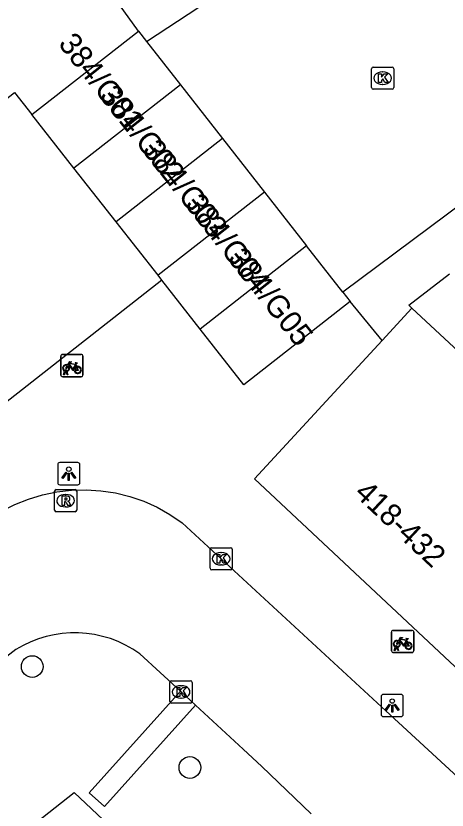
# Model space of a CAD drawing. Extents: x 159222 to 160346, y 381249 to 382166.
# Drawn here: x 159675.49 to 159694.93, y 381616.91 to 381652.7 of the extents above; entities that cross this region are included whole.
import ezdxf

# ---------------------------------------------------------------- set-up
doc = ezdxf.new("R2010")
doc.units = 0
for name, color, linetype in [('IMGEO_Boom', 7, 'Continuous'), ('IMGEO_Fietsenrek', 7, 'Continuous'), ('IMGEO_Groenvoorziening', 7, 'Continuous'), ('IMGEO_Kolk', 7, 'Continuous'), ('IMGEO_Lichtpunt', 7, 'Continuous'), ('IMGEO_Pand', 7, 'Continuous'), ('IMGEO_Pand_nummerreeks', 7, 'Continuous'), ('IMGEO_Rijbaan_lokaal_open', 7, 'Continuous'), ('IMGEO_Rioolput', 7, 'Continuous'), ('IMGEO_Voetpad_open', 7, 'Continuous')]:
    doc.layers.add(name, color=color, linetype=linetype)

msp = doc.modelspace()

# ---------------------------------------------------------------- linework, layer by layer
at = {"layer": 'IMGEO_Boom'}
for centre in [(159676.225, 381623.376), (159683.333, 381618.828)]:
    msp.add_circle(centre, 0.489, dxfattribs=at)
at = {"layer": 'IMGEO_Fietsenrek'}
for p, q in [((159677.514, 381636.518), (159677.514, 381637.359)), ((159677.514, 381637.359), (159677.514, 381636.518)), ((159677.589, 381637.443), (159678.43, 381637.443)), ((159678.43, 381637.443), (159677.589, 381637.443)), ((159678.514, 381637.368), (159678.514, 381636.527)), ((159678.514, 381636.527), (159678.514, 381637.368)), ((159678.201, 381636.992), (159678.237, 381636.897)), ((159677.641, 381636.527), (159677.68, 381636.687)), ((159677.675, 381636.527), (159677.641, 381636.527)), ((159677.71, 381636.675), (159677.675, 381636.527)), ((159677.752, 381636.699), (159677.751, 381636.703)), ((159677.793, 381636.527), (159677.759, 381636.669)), ((159677.783, 381636.71), (159677.784, 381636.703)), ((159677.791, 381636.673), (159677.826, 381636.527)), ((159677.826, 381636.527), (159677.793, 381636.527)), ((159678.439, 381636.443), (159677.598, 381636.443)), ((159677.598, 381636.443), (159678.439, 381636.443)), ((159692.424, 381624.085), (159692.424, 381624.926)), ((159692.424, 381624.926), (159692.424, 381624.085)), ((159692.499, 381625.01), (159693.34, 381625.01)), ((159693.34, 381625.01), (159692.499, 381625.01)), ((159693.424, 381624.935), (159693.424, 381624.094)), ((159693.424, 381624.094), (159693.424, 381624.935)), ((159693.111, 381624.559), (159693.147, 381624.464)), ((159693.349, 381624.01), (159692.508, 381624.01)), ((159692.508, 381624.01), (159693.349, 381624.01)), ((159692.551, 381624.094), (159692.59, 381624.254)), ((159692.585, 381624.094), (159692.551, 381624.094)), ((159692.62, 381624.242), (159692.585, 381624.094)), ((159692.662, 381624.266), (159692.661, 381624.27)), ((159692.703, 381624.094), (159692.669, 381624.236)), ((159692.693, 381624.277), (159692.694, 381624.27)), ((159692.701, 381624.24), (159692.736, 381624.094)), ((159692.736, 381624.094), (159692.703, 381624.094))]:
    msp.add_line(p, q, dxfattribs=at)
for points in [[(159677.848, 381636.917), (159677.796, 381636.827), (159677.756, 381636.802), (159677.757, 381636.849), (159677.812, 381636.943)], [(159677.827, 381636.969), (159677.922, 381637.133), (159678.008, 381637.119), (159678.01, 381637.11), (159677.954, 381637.099), (159677.927, 381637.054), (159678.183, 381637.013)], [(159678.123, 381636.725), (159678.073, 381636.725), (159677.882, 381636.976), (159677.863, 381636.944)], [(159678.17, 381636.988), (159677.913, 381637.029), (159677.896, 381637), (159678.063, 381636.78), (159678.17, 381636.988)], [(159678.218, 381636.89), (159678.188, 381636.967), (159678.079, 381636.749), (159678.122, 381636.749)], [(159678.152, 381636.749), (159678.272, 381636.748), (159678.228, 381636.862)], [(159678.248, 381636.869), (159678.303, 381636.724), (159678.153, 381636.724)], [(159678.183, 381637.013), (159678.208, 381637.062), (159678.202, 381637.066), (159678.179, 381637.07), (159678.167, 381637.077), (159678.166, 381637.08), (159678.168, 381637.085), (159678.263, 381637.07), (159678.265, 381637.06), (159678.255, 381637.047), (159678.243, 381637.041), (159678.229, 381637.047), (159678.201, 381636.992)], [(159692.737, 381624.536), (159692.832, 381624.7), (159692.918, 381624.686), (159692.92, 381624.677), (159692.864, 381624.666), (159692.837, 381624.621), (159693.093, 381624.58)], [(159692.758, 381624.484), (159692.706, 381624.394), (159692.666, 381624.369), (159692.667, 381624.416), (159692.722, 381624.51)], [(159693.033, 381624.292), (159692.983, 381624.292), (159692.792, 381624.543), (159692.773, 381624.511)], [(159693.08, 381624.555), (159692.823, 381624.596), (159692.806, 381624.567), (159692.973, 381624.347), (159693.08, 381624.555)], [(159693.128, 381624.457), (159693.098, 381624.534), (159692.989, 381624.316), (159693.032, 381624.316)], [(159693.062, 381624.316), (159693.182, 381624.315), (159693.138, 381624.429)], [(159693.158, 381624.436), (159693.213, 381624.291), (159693.063, 381624.291)], [(159693.093, 381624.58), (159693.118, 381624.629), (159693.112, 381624.633), (159693.089, 381624.637), (159693.077, 381624.644), (159693.076, 381624.647), (159693.078, 381624.652), (159693.173, 381624.637), (159693.175, 381624.627), (159693.165, 381624.614), (159693.153, 381624.608), (159693.139, 381624.614), (159693.111, 381624.559)]]:
    msp.add_lwpolyline(points, dxfattribs=at)
for centre, radius, start, end in [((159677.592, 381637.365), 0.0779, 92.4484, 184.2845), ((159677.592, 381637.365), 0.0779, 92.4484, 184.2845), ((159678.436, 381637.365), 0.0779, 2.4484, 94.2845), ((159678.436, 381637.365), 0.0779, 2.4484, 94.2845), ((159677.754, 381636.828), 0.159, 62.6766, 242.1369), ((159677.754, 381636.828), 0.129, 63.3192, 238.903), ((159677.754, 381636.828), 0.129, 283.6043, 43.4302), ((159677.754, 381636.828), 0.159, 283.5766, 46.6042), ((159678.281, 381636.744), 0.159, 113.3408, 178.3217), ((159678.281, 381636.744), 0.159, 187.0065, 105.7708), ((159678.281, 381636.744), 0.129, 113.923, 177.9556), ((159678.281, 381636.744), 0.129, 188.6715, 104.5883), ((159677.592, 381636.521), 0.0779, 182.4484, 274.2845), ((159677.592, 381636.521), 0.0779, 182.4484, 274.2845), ((159677.734, 381636.699), 0.0499, 12.8025, 158.6934), ((159677.754, 381636.828), 0.159, 253.9967, 271.7867), ((159677.734, 381636.699), 0.0174, 12.8025, 163.4502), ((159677.754, 381636.828), 0.129, 253.415, 269.0204), ((159678.436, 381636.521), 0.0779, 272.4484, 4.2845), ((159678.436, 381636.521), 0.0779, 272.4484, 4.2845), ((159692.502, 381624.932), 0.0779, 92.4484, 184.2845), ((159692.502, 381624.932), 0.0779, 92.4484, 184.2845), ((159693.346, 381624.932), 0.0779, 2.4484, 94.2845), ((159693.346, 381624.932), 0.0779, 2.4484, 94.2845), ((159692.664, 381624.395), 0.159, 62.6766, 242.1369), ((159692.664, 381624.395), 0.129, 63.3192, 238.903), ((159692.644, 381624.266), 0.0499, 12.8025, 158.6934), ((159692.664, 381624.395), 0.129, 283.6043, 43.4302), ((159692.664, 381624.395), 0.159, 283.5766, 46.6042), ((159693.191, 381624.311), 0.159, 113.3408, 178.3217), ((159693.191, 381624.311), 0.159, 187.0065, 105.7708), ((159693.191, 381624.311), 0.129, 113.923, 177.9556), ((159693.191, 381624.311), 0.129, 188.6715, 104.5883), ((159692.502, 381624.088), 0.0779, 182.4484, 274.2845), ((159692.502, 381624.088), 0.0779, 182.4484, 274.2845), ((159692.664, 381624.395), 0.159, 253.9967, 271.7867), ((159692.644, 381624.266), 0.0174, 12.8025, 163.4502), ((159692.664, 381624.395), 0.129, 253.415, 269.0204), ((159693.346, 381624.088), 0.0779, 272.4484, 4.2845), ((159693.346, 381624.088), 0.0779, 272.4484, 4.2845)]:
    msp.add_arc(centre, radius, start, end, dxfattribs=at)
at = {"layer": 'IMGEO_Groenvoorziening'}
msp.add_lwpolyline([(159666.889, 381608.847), (159678.112, 381617.696), (159680.462, 381615.488)], dxfattribs=at)
at = {"layer": 'IMGEO_Kolk'}
for p, q in [((159691.523, 381649.47), (159691.523, 381650.322)), ((159691.598, 381650.396), (159692.45, 381650.396)), ((159692.011, 381650.176), (159692.036, 381650.176)), ((159692.524, 381650.322), (159692.524, 381649.47)), ((159692.45, 381649.396), (159691.598, 381649.396)), ((159692.034, 381649.616), (159692.009, 381649.616)), ((159684.242, 381627.809), (159684.242, 381628.661)), ((159684.317, 381628.735), (159685.169, 381628.735)), ((159685.243, 381628.661), (159685.243, 381627.809)), ((159684.73, 381628.515), (159684.755, 381628.515)), ((159684.753, 381627.955), (159684.728, 381627.955)), ((159685.169, 381627.735), (159684.317, 381627.735)), ((159682.436, 381621.808), (159682.436, 381622.66)), ((159682.511, 381622.734), (159683.363, 381622.734)), ((159682.924, 381622.514), (159682.949, 381622.514)), ((159683.437, 381622.66), (159683.437, 381621.808)), ((159682.947, 381621.954), (159682.922, 381621.954)), ((159683.363, 381621.734), (159682.511, 381621.734))]:
    msp.add_line(p, q, dxfattribs=at)
for points in [[(159691.523, 381649.47), (159691.523, 381650.322)], [(159691.598, 381650.396), (159692.45, 381650.396)], [(159691.844, 381650.096), (159691.967, 381650.096), (159691.967, 381649.945), (159692.097, 381650.096), (159692.261, 381650.096), (159692.115, 381649.945), (159692.268, 381649.696), (159692.116, 381649.696), (159692.031, 381649.86), (159691.967, 381649.793), (159691.967, 381649.696), (159691.844, 381649.696), (159691.844, 381650.096)], [(159692.524, 381650.322), (159692.524, 381649.47)], [(159692.45, 381649.396), (159691.598, 381649.396)], [(159684.242, 381627.809), (159684.242, 381628.661)], [(159684.317, 381628.735), (159685.169, 381628.735)], [(159685.243, 381628.661), (159685.243, 381627.809)], [(159684.563, 381628.435), (159684.686, 381628.435), (159684.686, 381628.284), (159684.816, 381628.435), (159684.98, 381628.435), (159684.834, 381628.284), (159684.987, 381628.035), (159684.835, 381628.035), (159684.75, 381628.199), (159684.686, 381628.132), (159684.686, 381628.035), (159684.563, 381628.035), (159684.563, 381628.435)], [(159685.169, 381627.735), (159684.317, 381627.735)], [(159682.436, 381621.808), (159682.436, 381622.66)], [(159682.511, 381622.734), (159683.363, 381622.734)], [(159683.437, 381622.66), (159683.437, 381621.808)], [(159682.757, 381622.434), (159682.88, 381622.434), (159682.88, 381622.283), (159683.01, 381622.434), (159683.174, 381622.434), (159683.028, 381622.283), (159683.181, 381622.034), (159683.029, 381622.034), (159682.944, 381622.198), (159682.88, 381622.131), (159682.88, 381622.034), (159682.757, 381622.034), (159682.757, 381622.434)], [(159683.363, 381621.734), (159682.511, 381621.734)]]:
    msp.add_lwpolyline(points, dxfattribs=at)
for centre, start, end in [((159691.6, 381650.32), 91.552, 178.448), ((159691.6, 381650.32), 91.552, 178.448), ((159692.448, 381650.32), 1.552, 88.448), ((159692.448, 381650.32), 1.552, 88.448), ((159691.6, 381649.472), 181.552, 268.448), ((159691.6, 381649.472), 181.552, 268.448), ((159692.448, 381649.472), 271.552, 358.448), ((159692.448, 381649.472), 271.552, 358.448), ((159684.319, 381628.659), 91.552, 178.448), ((159684.319, 381628.659), 91.552, 178.448), ((159685.167, 381628.659), 1.552, 88.448), ((159685.167, 381628.659), 1.552, 88.448), ((159684.319, 381627.811), 181.552, 268.448), ((159684.319, 381627.811), 181.552, 268.448), ((159685.167, 381627.811), 271.552, 358.448), ((159685.167, 381627.811), 271.552, 358.448), ((159682.513, 381622.658), 91.552, 178.448), ((159682.513, 381622.658), 91.552, 178.448), ((159683.361, 381622.658), 1.552, 88.448), ((159683.361, 381622.658), 1.552, 88.448), ((159682.513, 381621.81), 181.552, 268.448), ((159682.513, 381621.81), 181.552, 268.448), ((159683.361, 381621.81), 271.552, 358.448), ((159683.361, 381621.81), 271.552, 358.448)]:
    msp.add_arc(centre, 0.0765, start, end, dxfattribs=at)
for centre, major_axis, ratio, start_param, end_param in [((159692.01, 381649.896), (-0.387, 0.002), 0.722429, 4.712389, 7.853982), ((159692.035, 381649.896), (-0.39, 0.002), 0.717154, 1.570796, 4.712389), ((159684.729, 381628.235), (-0.387, 0.002), 0.722429, 4.712389, 7.853982), ((159684.754, 381628.235), (-0.39, 0.002), 0.717154, 1.570796, 4.712389), ((159682.923, 381622.234), (-0.387, 0.002), 0.722429, 4.712389, 7.853982), ((159682.948, 381622.234), (-0.39, 0.002), 0.717154, 1.570796, 4.712389)]:
    msp.add_ellipse(centre, major_axis=major_axis, ratio=ratio, start_param=start_param, end_param=end_param, dxfattribs=at)
at = {"layer": 'IMGEO_Lichtpunt'}
for p, q in [((159678.277, 381632.57), (159677.469, 381632.57)), ((159678.277, 381632.57), (159677.469, 381632.57)), ((159677.375, 381632.475), (159677.375, 381631.668)), ((159677.375, 381632.475), (159677.375, 381631.668)), ((159678.371, 381631.668), (159678.371, 381632.475)), ((159678.371, 381631.668), (159678.371, 381632.475)), ((159677.469, 381631.574), (159678.277, 381631.574)), ((159677.469, 381631.574), (159678.277, 381631.574)), ((159691.957, 381622.025), (159691.957, 381621.218)), ((159691.957, 381622.025), (159691.957, 381621.218)), ((159692.859, 381622.12), (159692.051, 381622.12)), ((159692.859, 381622.12), (159692.051, 381622.12)), ((159692.953, 381621.218), (159692.953, 381622.025)), ((159692.953, 381621.218), (159692.953, 381622.025)), ((159692.051, 381621.124), (159692.859, 381621.124)), ((159692.051, 381621.124), (159692.859, 381621.124))]:
    msp.add_line(p, q, dxfattribs=at)
for points in [[(159677.749, 381632.139), (159677.788, 381632.111), (159677.6, 381631.849), (159677.562, 381631.876), (159677.749, 381632.139)], [(159677.851, 381632.091), (159677.898, 381632.091), (159677.898, 381631.769), (159677.851, 381631.769), (159677.851, 381632.091)], [(159677.961, 381632.111), (159677.999, 381632.138), (159678.186, 381631.876), (159678.147, 381631.848), (159677.961, 381632.111)], [(159692.331, 381621.689), (159692.37, 381621.661), (159692.182, 381621.399), (159692.144, 381621.426), (159692.331, 381621.689)], [(159692.433, 381621.641), (159692.48, 381621.641), (159692.48, 381621.319), (159692.433, 381621.319), (159692.433, 381621.641)], [(159692.543, 381621.661), (159692.581, 381621.688), (159692.768, 381621.426), (159692.729, 381621.398), (159692.543, 381621.661)]]:
    msp.add_lwpolyline(points, dxfattribs=at)
for centre in [(159677.874, 381632.273), (159692.456, 381621.823)]:
    msp.add_circle(centre, 0.0994, dxfattribs=at)
for centre, start, end in [((159677.469, 381632.475), 90, 180), ((159677.469, 381632.475), 90, 180), ((159678.277, 381632.475), 0, 90), ((159678.277, 381632.475), 0, 90), ((159677.469, 381631.668), 180, 270), ((159677.469, 381631.668), 180, 270), ((159678.277, 381631.668), 270, 0), ((159678.277, 381631.668), 270, 360), ((159692.051, 381622.025), 90, 180), ((159692.051, 381622.025), 90, 180), ((159692.859, 381622.025), 0, 90), ((159692.859, 381622.025), 0, 90), ((159692.051, 381621.218), 180, 270), ((159692.051, 381621.218), 180, 270), ((159692.859, 381621.218), 270, 0), ((159692.859, 381621.218), 270, 360)]:
    msp.add_arc(centre, 0.0946, start, end, dxfattribs=at)
at = {"layer": 'IMGEO_Pand'}
for points in [[(159676.208, 381648.256), (159681.011, 381652.018)], [(159681.011, 381652.018), (159681.38, 381651.547)], [(159681.38, 381651.547), (159682.907, 381649.597)], [(159682.907, 381649.597), (159678.108, 381645.838)], [(159682.907, 381649.597), (159684.803, 381647.176)], [(159672.749, 381647.16), (159675.425, 381649.256), (159676.208, 381648.256)], [(159678.108, 381645.838), (159676.208, 381648.256)], [(159684.803, 381647.176), (159680.008, 381643.421)], [(159684.803, 381647.176), (159686.691, 381644.766)], [(159680.008, 381643.421), (159678.108, 381645.838)], [(159686.691, 381644.766), (159681.899, 381641.013)], [(159686.691, 381644.766), (159688.595, 381642.335)], [(159681.899, 381641.013), (159680.008, 381643.421)], [(159688.595, 381642.335), (159683.804, 381638.582)], [(159690.231, 381640.246), (159688.595, 381642.335)], [(159682.069, 381640.797), (159670.12, 381631.438)], [(159682.069, 381640.797), (159681.899, 381641.013)], [(159683.804, 381638.582), (159682.069, 381640.797)], [(159690.231, 381640.246), (159690.556, 381639.831)], [(159690.556, 381639.831), (159685.765, 381636.079), (159683.804, 381638.582)], [(159691.997, 381638.077), (159693.343, 381639.536)], [(159704.334, 381629.328), (159693.343, 381639.536)], [(159697.195, 381621.587), (159686.25, 381631.845), (159691.997, 381638.077)]]:
    msp.add_lwpolyline(points, dxfattribs=at)
at = {"layer": 'IMGEO_Rijbaan_lokaal_open'}
for points in [[(159681.38, 381651.547), (159686.578, 381654.975), (159698.504, 381664.326), (159725.995, 381685.842), (159726.077, 381685.887), (159726.578, 381686.129), (159727.1, 381686.326), (159727.636, 381686.475), (159728.184, 381686.575), (159728.739, 381686.627), (159729.296, 381686.628), (159729.85, 381686.58), (159730.399, 381686.482), (159730.936, 381686.336), (159731.459, 381686.142), (159731.961, 381685.903), (159732.441, 381685.619), (159732.893, 381685.294), (159765.564, 381655.029), (159765.97, 381654.692), (159766.405, 381654.392), (159766.864, 381654.132), (159767.345, 381653.914), (159767.844, 381653.74)], [(159701.061, 381645.68), (159700.652, 381645.814), (159700.232, 381645.91), (159699.805, 381645.969), (159699.375, 381645.989), (159698.945, 381645.971), (159698.518, 381645.914), (159698.098, 381645.82), (159697.688, 381645.688), (159697.301, 381645.525), (159690.231, 381640.246)], [(159638.593, 381602.067), (159674.232, 381629.981), (159674.292, 381630.023), (159674.853, 381630.376), (159675.443, 381630.678), (159676.058, 381630.926), (159676.692, 381631.119), (159677.342, 381631.253), (159678, 381631.329), (159678.663, 381631.346), (159679.325, 381631.304), (159679.98, 381631.203), (159680.624, 381631.044), (159681.251, 381630.827), (159681.856, 381630.556), (159682.434, 381630.232), (159682.981, 381629.857), (159692.174, 381621.387), (159699.994, 381614.171), (159717.156, 381598.135)], [(159675.488, 381624.14), (159666.976, 381617.546)], [(159682.91, 381622.264), (159681.078, 381623.956)], [(159682.91, 381622.264), (159683.594, 381621.632)], [(159688.806, 381616.746), (159686.583, 381618.876), (159685.737, 381619.653), (159683.594, 381621.632)]]:
    msp.add_lwpolyline(points, dxfattribs=at)
msp.add_arc((159678.145, 381619.848), 5.048, 54.4717, 121.7578, dxfattribs=at)
at = {"layer": 'IMGEO_Rioolput'}
for p, q in [((159677.229, 381630.428), (159677.229, 381631.28)), ((159677.304, 381631.354), (159678.156, 381631.354)), ((159677.717, 381631.134), (159677.742, 381631.134)), ((159678.23, 381631.28), (159678.23, 381630.428)), ((159677.74, 381630.574), (159677.715, 381630.574)), ((159678.156, 381630.354), (159677.304, 381630.354))]:
    msp.add_line(p, q, dxfattribs=at)
for points in [[(159677.229, 381630.428), (159677.229, 381631.28)], [(159677.304, 381631.354), (159678.156, 381631.354)], [(159678.23, 381631.28), (159678.23, 381630.428)], [(159677.818, 381631.052), (159677.566, 381631.054), (159677.566, 381630.654)], [(159677.566, 381630.654), (159677.69, 381630.654), (159677.69, 381630.816), (159677.701, 381630.816)], [(159677.744, 381630.973), (159677.69, 381630.973), (159677.69, 381630.892)], [(159677.69, 381630.892), (159677.742, 381630.892)], [(159677.748, 381630.787), (159677.819, 381630.654), (159677.959, 381630.654), (159677.894, 381630.78)], [(159678.156, 381630.354), (159677.304, 381630.354)]]:
    msp.add_lwpolyline(points, dxfattribs=at)
for centre, radius, start, end in [((159677.306, 381631.278), 0.0765, 91.552, 178.448), ((159677.306, 381631.278), 0.0765, 91.552, 178.448), ((159678.154, 381631.278), 0.0765, 1.552, 88.448), ((159678.154, 381631.278), 0.0765, 1.552, 88.448), ((159677.7, 381630.763), 0.0533, 26.0293, 88.6989), ((159677.726, 381631.081), 0.19, 274.7715, 282.9687), ((159677.75, 381630.877), 0.0964, 77.0061, 93.1865), ((159677.764, 381630.934), 0.0378, 276.6634, 79.6772), ((159677.817, 381630.942), 0.109, 350.3612, 89.416), ((159677.815, 381630.942), 0.112, 277.5842, 350.9817), ((159677.799, 381630.727), 0.108, 29.5134, 73.7905), ((159677.306, 381630.43), 0.0765, 181.552, 268.448), ((159677.306, 381630.43), 0.0765, 181.552, 268.448), ((159678.154, 381630.43), 0.0765, 271.552, 358.448), ((159678.154, 381630.43), 0.0765, 271.552, 358.448)]:
    msp.add_arc(centre, radius, start, end, dxfattribs=at)
for centre, major_axis, ratio, start_param, end_param in [((159677.716, 381630.854), (-0.387, 0.002), 0.722429, 4.712389, 7.853982), ((159677.741, 381630.854), (-0.39, 0.002), 0.717154, 1.570796, 4.712389)]:
    msp.add_ellipse(centre, major_axis=major_axis, ratio=ratio, start_param=start_param, end_param=end_param, dxfattribs=at)
at = {"layer": 'IMGEO_Voetpad_open'}
for points in [[(159681.011, 381652.018), (159680.162, 381653.201), (159683.008, 381655.483)], [(159693.343, 381639.536), (159693.2, 381639.672), (159695.046, 381641.083)], [(159691.997, 381638.077), (159690.556, 381639.831)], [(159683.594, 381621.632), (159679.491, 381617.068), (159678.799, 381617.69), (159682.91, 381622.264)]]:
    msp.add_lwpolyline(points, dxfattribs=at)

# ---------------------------------------------------------------- texts
at = {"layer": 'IMGEO_Pand_nummerreeks'}
for s, rotation, p in [('384/G01', 308.2676, (159677.364, 381651.436)), ('384/G02', 308.2676, (159679.218, 381649.086)), ('384/G03', 308.2676, (159681.148, 381646.639)), ('384/G04', 308.2676, (159683.075, 381644.197)), ('384/G05', 308.2676, (159685.001, 381641.755)), ('418-432', 316.8562, (159690.699, 381631.129))]:
    msp.add_text(s, height=1, rotation=rotation, dxfattribs=at).set_placement(p)

doc.saveas('drawing.dxf')
